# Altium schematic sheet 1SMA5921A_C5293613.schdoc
size 127 x 101 mm
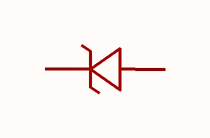
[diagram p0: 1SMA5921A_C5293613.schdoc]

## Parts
D?  1sma5921a_c5293613  [SMA_L4.3-W2.6-LS5.2-RD]  (value not drawn)

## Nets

Not connected (* = marked no-connect by the designer): D? 1(K) 2(A)

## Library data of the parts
D? = 1sma5921a_c5293613: 二极管配置:1个独立式;稳压值(标称值):6.8V;稳压值(范围):6.46V~7.14V;耗散功率(Pd):1.5W;; Manufacturer: CJ(江苏长电/长晶); AddInBom: yes; ModelId: e3551acb3c5a4975a5e9d36087fe1fa2; ModelTransform: 185.039,102.362,0,0,0,0,0,0,0; Diode Configuration: 1个独立式; Zener Voltage(Nom): 6.8V; Reverse Leakage Current (Ir): 2.5uA; Pd - Power Dissipation: 1.5W; Impedance(Zzt): 2.5Ω; Impedance(Zzk): 200Ω; Operating Junction Temperature Range: -55℃~+150℃; Tolerance: ±5%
